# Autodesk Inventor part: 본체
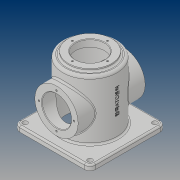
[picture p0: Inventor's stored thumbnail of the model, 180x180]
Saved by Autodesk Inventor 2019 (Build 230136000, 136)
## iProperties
Created: 2019-03
Part Number: 본체
Material: 일반
Document SubType Name: Modeling
Designer: PC312-10
Density: 1 g/cm^3
Appearance: 기본값
Author: PC312-10
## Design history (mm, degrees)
sketch "스케치1"
  geometry: L1 (0, 0)-(0, 120); L2 (0, 112)-(-45, 112); L3 (-45, 112)-(-45, 0); L4 (-45, 0)-(-50, 0); L5 (-50, 0)-(-50, 120); L6 (-50, 120)-(0, 120)
  constraints: 12 end point, 3 horizontal, 3 vertical, 2 point on line
  dimensions: "d0" = 120 distance of L1.end L1.start; "d2" = 100 diameter of L5 L1; "d3" = 90 diameter of L3 L1; "d4" = 112 distance between parallel lines of L4 L2
revolve "회전1" sketch "스케치1" stored, may be unused: angle "d5" = 90 deg
sketch "스케치2"
  geometry: C1 r 40 at (0, 0); 1 further point
  constraints: 1 centre point, 1 coincident
  dimensions: "d6" = 80 diameter of C1
extrude "돌출1" join sketch "스케치2" distance "d7" = 5; taper "d8" = 0 deg
sketch "스케치3"
  geometry: C1 r 40 at (0, 0) reference; C2 r 27 at (0, 0); 1 further point
  constraints: 1 centre point, 1 coincident
  dimensions: "d9" = 54 diameter of C2
extrude "돌출2" cut sketch "스케치3" extent not by distance; stored distance "d10" = 5; taper "d11" = 0 deg
sketch "스케치4"
  geometry: L1 (-70, -70)-(70, -70); L2 (70, -70)-(70, 70); L3 (70, 70)-(-70, 70); L4 (-70, 70)-(-70, -70); L5 (-70, -70)-(70, 70); L6 (70, -70)-(-70, 70); C1 r 50 at (0, 0) reference; 1 further point
  constraints: 12 end point, 2 midpoint, 2 parallel, 1 horizontal, 1 perpendicular
  dimensions: "d12" = 140 distance of L3.end L2.end; "d13" = 140 distance of L2.end L1.end
extrude "돌출3" join sketch "스케치4" distance "d14" = 10; taper "d15" = 0 deg
fillet "모깎기1" dims "d16" = 10
sketch "스케치5"
  geometry: C1 r 4.5 at (-60, 60); C2 r 4.5 at (60, 60); C3 r 4.5 at (60, -60); C4 r 4.5 at (-60, -60); A1 r 10 centre (-60, 60) between (-60, 70) and (-70, 60) reference; A2 r 10 centre (60, 60) between (70, 60) and (60, 70) reference; A3 r 10 centre (60, -60) between (60, -70) and (70, -60) reference; A4 r 10 centre (-60, -60) between (-70, -60) and (-60, -70) reference; 1 further point
  constraints: 4 centre point, 4 coincident
  dimensions: "d17" = 9 diameter of C1; "d18" = 9 diameter of C2; "d19" = 9 diameter of C3; "d20" = 9 diameter of C4
extrude "돌출4" cut sketch "스케치5" extent not by distance; stored distance "d21" = 10; taper "d22" = 0 deg
node "작업 평면1"
sketch "스케치6"
  geometry: L1 (60, 0)-(-60, 0) reference; C1 r 40 at (0, 60); 2 further points
  constraints: 1 centre point, 1 midpoint, 1 vertical alignment
  dimensions: "d24" = 80 diameter of C1; "d25" = 60 distance from line of L1 C1.centre
extrude "돌출5" join sketch "스케치6" stored distance "d26" = 10; taper "d27" = 0 deg
sketch "스케치7"
  geometry: C1 r 40 at (0, 0) reference; C2 r 27 at (0, 0); 1 further point
  constraints: 1 centre point, 1 coincident
  dimensions: "d28" = 54 diameter of C2
extrude "돌출6" cut sketch "스케치7" extent not by distance; stored distance "d29" = 0; taper "d30" = 0 deg
sketch "스케치8"
  geometry: C1 r 40 at (0, 0) reference; 2 further points
  constraints: 1 vertical alignment
  dimensions: "d31" = 32.5 distance of C1.centre point (0, 32.5)
hole "구멍1" sketch "스케치8" at (0, 32.5) diameter "d32" = 3.242; stored, may be unused: countersink angle "d36" = 90 deg, drill point angle "d38" = 118 deg; dims "d33" = 8, "d34" = 4, "d35" = 2, "d37" = 10
sketch "스케치9"
  geometry: 2 further points
  constraints: 1 vertical alignment
  dimensions: "d42" = 32.5 distance of point (0, 0) point (0, 32.5)
hole "구멍2" sketch "스케치9" at (0, 32.5) diameter "d43" = 3.242; stored, may be unused: countersink angle "d47" = 90 deg, drill point angle "d49" = 118 deg; dims "d44" = 8, "d45" = 4, "d46" = 2, "d48" = 10
chamfer "모따기1" distance "d53" = 1; stored, may be unused: second distance "d54" = 2, angle "d55" = 45 deg
fillet "모깎기2" dims "d56" = 3
fillet "모깎기3" dims "d57" = 3
fillet "모깎기4" dims "d58" = 5
fillet "모깎기5" dims "d59" = 3
node "작업 평면2"
sketch "스케치11"
  geometry: L1 (0, -60)-(0, 60) reference; 3 further points
  constraints: 1 horizontal alignment, 1 midpoint, 1 other
  dimensions: "d61" = 70 distance from line of L1 point (70, 0)
feature "엠보싱1" sketch "스케치11" dims "d0" = 120, "d2" = 100, "d3" = 90, "d4" = 112, "d62" = 0.5, "d63" = 0
node "솔리드1"
mirror "미러1"
pattern_circular "원형 패턴1" dims angle "d40" = 360 deg
mirror "미러2"
pattern_circular "원형 패턴2" dims angle "d51" = 360 deg
other parameters: "d23" = 62, "d60" = 83.25
